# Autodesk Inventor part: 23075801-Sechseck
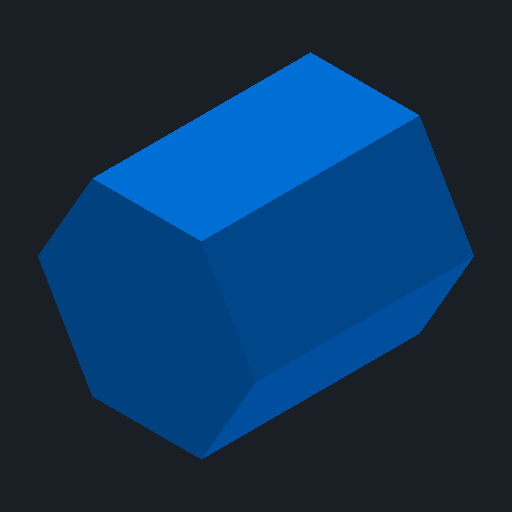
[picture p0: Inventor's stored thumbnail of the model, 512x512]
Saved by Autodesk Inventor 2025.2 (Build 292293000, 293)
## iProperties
Company: Ed. Züblin AG
Created: 2025-03
Part Number: 23075801-Sechseck
Material: Stahlbeton C30/37
Document SubType Name: Modeling
Designer: FrodlSte
Mass: 1.6238e+06 g
Surface Area: 42990.4 cm^2
Volume: 649519 cm^3
Density: 2.5 g/cm^3
Appearance: Beton C30/37
Description: Rohrleitung
z_Bereich: Tunnelbau
z_Direktion: Tief- und Tunnelbau
z_Konzerneinheit: Zentrale Technik
z_Matchkey: =<z_Matchkey_010>_<z_Matchkey_020>_<z_Matchkey_030>_<z_Matchkey_040>_<z_Matchkey_050>_<z_Matchkey_060>_<z_Matchkey_070>_<z_Matchkey_080>_<z_Matchkey_090>_<z_Mat
cpiComponentType: Attribut
cpiFitMatchkey: =<z_Matchkey>
z_Matchkey_010: xxxxx
z_Matchkey_020: 5DTUB
z_Matchkey_030: xxx
z_Matchkey_040: xxx
z_Matchkey_050: xxx
z_Matchkey_060: xxx
z_Matchkey_070: xxx
z_Matchkey_080: xxx
z_Matchkey_090: xxx
z_Matchkey_100: xxx
z_Matchkey_110: xxx
z_Matchkey_120: xxxxxxx
z_Matchkey_130: xxxx
z_Matchkey_140: xxxx
DocNumber: 23075801-Sechseck.ipt
Folder: DL23075801-DE-Pfaffensteigtunnel\BIM\Testmodell
VDS_Category: 09 - BIM - Konstruktion
DBSet_Element:010_Eigentuemer: DBI
DBSet_Element:020_Autor: VP2ZB
DBSet_Element:030_Projektnummer: G.016268527
DBSet_Element:040_Bereich: 01
DBSet_Element:050_Vertragspartner: 02
DBSet_Element:060_Gewerk: 32
DBSet_Element:070_Bauwerk: SB
DBSet_Element:100_Gruppe: Drainage
DBSet_Element:110_Element: Rohrleitung
DBSet_Element:120_Elementtyp: Anschlussleitung
DBSet_Element:130_Identifikationsnummer: ND
DBSet_Element:140_Position_1: SOHL
DBSet_Element:150_Position_2: ND
DBSet_Element:160_PUID: ND
DBSet_Element:170_Hauptmaterialitaet: ND
DBSet_Element:171_Materialindikator_1: ND
DBSet_Element:172_Materialindikator_2: ND
DBSet_Geometrie:Laenge: 2.0
DBSet_Geometrie:Nenndurchmesser_mm: 250.0
DBSet_TP:Status: NBA
DBSet_TU_Rohrleitung:Rohrsteifigkeit: ND
DBSet_TU_Rohrleitung:Rohrtyp: Vollsickerrohr
DBSet_TU_Rohrleitung:Schlitzweite: ND
z_DBSet_Element:010_Eigentuemer: DBInfraGo
z_DBSet_Element:020_Autor: Vertragspartner 2 ZB
z_DBSet_Element:030_Projektnummer: Gaeubahn Nord HP Goldberg (DBnfraGO, BK11)
z_DBSet_Element:040_Bereich: PFA 1 Tunnel
z_DBSet_Element:050_Vertragspartner: Tunnel
z_DBSet_Element:060_Gewerk: Tunnelbau
z_DBSet_Element:070_Bauwerk: SBW-Tu
z_DBSet_Element:080_Bauwerksnummer: zzz (leer)
z_DBSet_Element:090_Bezeichnung: zzz (leer)
z_DBSet_Element:100_Gruppe: Drainage
z_DBSet_Element:110_Element: Rohrleitung
z_DBSet_Element:120_Elementtyp: Anschlussleitung
z_DBSet_Element:130_Identifikationsnummer: nicht definiert
z_DBSet_Element:140_Position_1: Sohle
z_DBSet_Element:150_Position_2: Nicht definiert
z_DBSet_Element:160_PUID: nicht definiert
z_DBSet_Element:170_Hauptmaterialitaet: nicht definiert
z_DBSet_Element:171_Materialindikator_1: nicht definiert
z_DBSet_Element:172_Materialindikator_2: nicht definiert
z_DBSet_Geometrie:Laenge: 2,000 m
z_DBSet_Geometrie:Nenndurchmesser_mm: 250,000 mm
z_DBSet_Position:Streckenachse: zzz (leer)
z_DBSet_Position:Streckenkilometer_Anfang: -11111,000 oE
z_DBSet_Position:Streckenkilometer_Ende: -11111,000 oE
z_DBSet_Position:Tunnelachse: zzz (leer)
z_DBSet_Position:Tunnelmeter_Anfang: -11111,000 oE
z_DBSet_Position:Tunnelmeter_Ende: -11111,000 oE
z_DBSet_TP:Status: Neubau
z_DBSet_TU_Rohrleitung:Rohrsteifigkeit: Nicht definiert
z_DBSet_TU_Rohrleitung:Rohrtyp: Vollsickerrohr
z_DBSet_TU_Rohrleitung:Schlitzweite: Nicht definiert
z_DBSet_EEE: EEE
Author: FrodlSte
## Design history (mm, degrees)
derived "23075801-Skelett.ipt"
node "Sechseck"
node "Volumenkörpern"
node "Oberflächenkörpern"
feature "Sechseck::23075801-Skelett.ipt"
tag "Bezeichnung1"
